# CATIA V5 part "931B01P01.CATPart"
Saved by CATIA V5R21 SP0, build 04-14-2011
Part number: 931B01P01
Bounding box of the stored display mesh (mm): x -17.1 to 17.1, y -76.2 to 76.2, z -4.4 to 4.4
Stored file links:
  C:\Users\ALI OZGUN\Desktop\alhan\931B01P01.CATPart
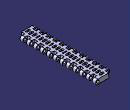
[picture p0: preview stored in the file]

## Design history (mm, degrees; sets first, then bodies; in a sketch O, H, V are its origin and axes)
Body1 (main body)
  Sketch1 on zx-plane, origin (0, 0, 0), H (-1, 0, 0), V (0, 0, 1)
    construction line L1 (-12.7, 0) -> (12.7, 0)
    point P1 (-12.7, 0)
    line L2 (-12.7, 4.4) -> (12.7, 4.4)
    line L3 (12.7, -4.4) -> (-12.7, -4.4)
    arc A1 centre (12.7, 0) radius 4.4 from (12.7, 4.4) to (12.7, -4.4) cw
    arc A2 centre (-12.7, 0) radius 4.4 from (-12.7, -4.4) to (-12.7, 4.4) cw
    distance L1 L2 = 4.4
    length L1 = 25.4
    distance P1 V = 12.7
    coincidence: P1 H
    horizontal: L1 H
    tangency: A1 L2, A2 L2, A1 L3, A2 L3
  Pad1: profile Sketch1, direction (0, 1, 0), length 76.2, mirrored extent
  Sketch2 on face of Pad1 from Sketch1.L2, origin (0, 0, 4.4), H (1, 0, 0), V (0, 1, 0)
    line L1 (-22.3127, -63.5) -> (-9.75, -63.5)
    line L2 (-9.75, -63.5) -> (-9.75, -70.6)
    line L3 (-9.75, -70.6) -> (-22.3127, -70.6)
    line L4 (-22.3127, -70.6) -> (-22.3127, -63.5)
    line L5 (24.6678, -76.95) -> (9.75, -76.95)
    line L6 (9.75, -76.95) -> (9.75, -69.85)
    line L7 (9.75, -69.85) -> (24.6678, -69.85)
    line L8 (24.6678, -69.85) -> (24.6678, -76.95)
    reference projected line E1 (-12.7, -76.2) -> (12.7, -76.2) from edge [start face of Pad1 | face of Pad1 from Sketch1.L2]
    reference projected line E2 (-12.7, -76.2) -> (12.7, -76.2) from edge [start face of Pad1 | face of Pad1 from Sketch1.L2]
    distance L3 E1 = 5.6
    length L4 = 7.1
    distance L7 L5 = 7.1
    distance L5 E2 = 0.75
    distance L2 L6 = 19.5
    distance L2 V = 9.75
    horizontal: L1 H, L3 H, L5 H, L7 H
    vertical: L2 V, L4 V, L6 V, L8 V
  Pocket1: profile Sketch2, direction (0, 0, -1), length 76.2
  RectPattern1: of Pocket1, direction 1 instances 12, spacing 12.7, along axis of face of Pad1 from Sketch1.A2
  Sketch3 on face of Pad1 from Sketch1.L3, origin (0, 0, -4.4), H (1, 0, 0), V (0, -1, 0)
    line L1 (-6.5, -54.6) -> (6.5, -54.6)
    line L2 (6.5, -54.6) -> (6.5, -73.7)
    line L3 (6.5, -73.7) -> (-6.5, -73.7)
    line L4 (-6.5, -73.7) -> (-6.5, -54.6)
    construction line L5 (-4.5, -51.1) -> (4.5, -51.1)
    point P5 (-4.5, -51.1)
    line L6 (-4.5, -49.6) -> (4.5, -49.6)
    line L7 (4.5, -52.6) -> (-4.5, -52.6)
    arc A1 centre (4.5, -51.1) radius 1.5 from (4.5, -49.6) to (4.5, -52.6) cw
    arc A2 centre (-4.5, -51.1) radius 1.5 from (-4.5, -52.6) to (-4.5, -49.6) cw
    reference projected line E1 (12.7, -76.2) -> (-12.7, -76.2) from edge [face of Pad1 from Sketch1.L3 | end face of Pad1]
    distance L5 L6 = 1.5
    distance L1 L3 = 19.1
    distance L4 L2 = 13
    distance L4 V = 6.5
    distance E1 L3 = 2.5
    distance P5 V = 4.5
    length L5 = 9
    distance L7 L1 = 2
    horizontal: L1 H, L3 H, L5 H
    vertical: L2 V, L4 V
    tangency: A1 L6, A2 L6, A1 L7, A2 L7
  Pocket2: profile Sketch3, direction (0, 0, 1), length 6
  RectPattern2: of Pocket2, direction 1 instances 6, spacing 25.8, along axis of face of Pad1 from Sketch1.A2 reversed
  Sketch4 on zx-plane, origin (0, 0, 0), H (-1, 0, 0), V (0, 0, 1)
    circle A1 centre (12.7, 0) radius 2.3
    point P1 (12.7, 0)
    circle A2 centre (-12.7, 0) radius 2.3
    point P2 (-12.7, 0)
    reference projected arc E1 centre (12.7, 0) radius 4.4 from (12.7, -4.4) to (12.7, 4.4) ccw from edge [face of RectPattern1 | face of Pad1 from Sketch1.A1]
    reference projected arc E2 centre (-12.7, 0) radius 4.4 from (-12.7, 4.4) to (-12.7, -4.4) ccw from edge [face of Pad1 from Sketch1.A2 | end face of Pad1]
    radius A1 = 2.3
    radius A2 = 2.3
    coincidence: P1 H, P2 H
    concentricity: P1 E1, A2 E2
  Pocket3: profile Sketch4, direction (0, -1, 0), length 97.8, mirrored extent
  Body2
    Solid1: linked copy from another document
    Symmetry1: Reference yz-plane, ToTransfor Solid1
    Translate1: Direction edge [face of Pocket1 from Sketch2.L2 | face of Pad1 from Sketch1.L3], Length 6.35, ToTransfor Symmetry1
    Body3
      Sketch5 on face of RectPattern1, origin (9.75, 0, 0), H (0, 1, 0), V (0, 0, 1)
      Pad2: profile Sketch5, direction (1, 0, 0), length 12
      Sketch6 on face of Pad2, origin (0, 69.85, 0), H (-1, 0, 0), V (0, 0, 1)
        point P2 (-21.75, 4.4)
        arc A1 centre (-16.4898, 1.5645) radius 9 from (-9.75, -4.4) to (-7.9481, 4.4) ccw
        point P8 (-21.75, 4.4)
        construction line L1 (-9.75, 4.4) -> (-21.75, 4.4)
        line L2 (-7.9481, 4.4) -> (-21.75, 4.4)
        line L3 (-9.75, -4.4) -> (-21.75, -4.4)
        line L4 (-21.75, -4.4) -> (-21.75, 4.4)
        radius A1 = 9
        coincidence: P2 P8
      Pad3: profile Sketch6, direction (0, 1, 0), up to face of Pad2
      RectPattern3: of the body so far, direction 1 instances 12, spacing 12.7, along edge [face of Pad3 | face of Pad3] reversed
    Add1: tool Body3
  Remove1: tool Body2
  Sketch7 on face of Pad1 from Sketch1.L2, origin (0, 0, 4.4), H (1, 0, 0), V (0, 1, 0)
    construction line L1 (2.4, -71.6) -> (-2.4, -71.6)
    point P1 (2.4, -71.6)
    point P2 (-2.4, -71.6)
    line L2 (2.4, -73.5) -> (-2.4, -73.5)
    line L3 (-2.4, -69.7) -> (2.4, -69.7)
    arc A1 centre (-2.4, -71.6) radius 1.9 from (-2.4, -73.5) to (-2.4, -69.7) cw
    arc A2 centre (2.4, -71.6) radius 1.9 from (2.4, -69.7) to (2.4, -73.5) cw
    construction line L4 (2.4, -65.1) -> (-2.4, -65.1)
    point P7 (2.4, -65.1)
    point P8 (-2.4, -65.1)
    line L5 (2.4, -67) -> (-2.4, -67)
    line L6 (-2.4, -63.2) -> (2.4, -63.2)
    arc A3 centre (-2.4, -65.1) radius 1.9 from (-2.4, -67) to (-2.4, -63.2) cw
    arc A4 centre (2.4, -65.1) radius 1.9 from (2.4, -63.2) to (2.4, -67) cw
    construction line L7 (2.4, -58.6) -> (-2.4, -58.6)
    point P13 (2.4, -58.6)
    point P14 (-2.4, -58.6)
    line L8 (2.4, -60.5) -> (-2.4, -60.5)
    line L9 (-2.4, -56.7) -> (2.4, -56.7)
    arc A5 centre (-2.4, -58.6) radius 1.9 from (-2.4, -60.5) to (-2.4, -56.7) cw
    arc A6 centre (2.4, -58.6) radius 1.9 from (2.4, -56.7) to (2.4, -60.5) cw
    construction line L10 (3.3, -52.1) -> (-3.3, -52.1)
    line L11 (3.3, -53.1) -> (-3.3, -53.1)
    line L12 (-3.3, -51.1) -> (3.3, -51.1)
    arc A7 centre (-3.3, -52.1) radius 1 from (-3.3, -53.1) to (-3.3, -51.1) cw
    arc A8 centre (3.3, -52.1) radius 1 from (3.3, -51.1) to (3.3, -53.1) cw
    reference intersected line E1 (12.7, -76.2) -> (-12.7, -76.2) from start face of Pad1
    reference projected line E2 (4.5, -53.6) -> (-4.5, -53.6) from edge [face of Pad1 from Sketch1.L3 | face of RectPattern2]
    distance L1 L2 = 1.9
    distance L4 L5 = 1.9
    distance L7 L8 = 1.9
    distance L10 L11 = 1
    distance L5 L3 = 2.7
    distance L8 L6 = 2.7
    length L1 = 4.8
    distance L2 E1 = 2.7
    distance P7 V = 2.4
    distance P13 P1 H = 0
    distance P7 P1 H = 0
    distance P8 P2 H = 0
    distance P14 P2 H = 0
    distance L10 E2 = 1.5
    distance A7 A5 H = 0
    distance A8 A6 H = 0
    horizontal: L1 H, L4 H, L7 H, L10 H
    tangency: A1 L2, A2 L2, A1 L3, A2 L3, A3 L5, A4 L5, A3 L6, A4 L6, A5 L8, A6 L8, A5 L9, A6 L9, A7 L11, A8 L11, A7 L12, A8 L12
  Pocket4: profile Sketch7, direction (0, 0, -1), length 12
  RectPattern4: of Pocket4, direction 1 instances 6, spacing 25.8, along axis of face of Pad1 from Sketch1.A1
  RemoveFace1: RemoveFaces (face of RectPattern4; face of RectPattern4; face of RectPattern4)
Body4
  Solid2: linked copy from another document
  Translate2: Direction yz-plane, Length 25.4, ToTransfor Solid2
